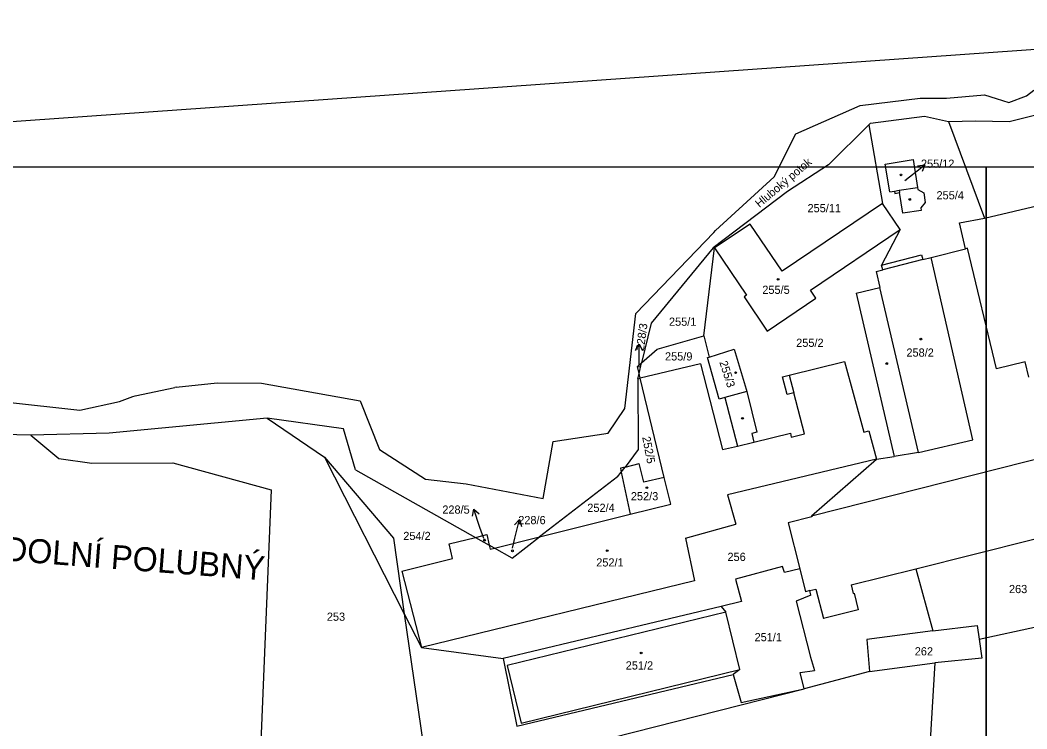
# Model space of a CAD drawing. Extents: x -670359 to -668019, y -978807 to -976674.
# Drawn here: x -669575.5 to -669366.6, y -977116.7 to -976969.5 of the extents above; entities that cross this region are included whole.
import ezdxf

# ---------------------------------------------------------------- set-up
doc = ezdxf.new("R2010")
doc.units = 0
for name, color, linetype in [('Hranice kat_území', 7, 'Continuous'), ('Hranice parcel', 7, 'Continuous'), ('ML1000', 7, 'Continuous'), ('Parcelní čísla', 7, 'Continuous'), ('Pop  PČ popisy', 7, 'Continuous'), ('SO 11-10-01', 7, 'Continuous'), ('Vnitřní kresba', 7, 'Continuous'), ('Značky budov', 7, 'Continuous'), ('Značky kultur', 7, 'Continuous')]:
    doc.layers.add(name, color=color, linetype=linetype)

msp = doc.modelspace()

# ---------------------------------------------------------------- linework, layer by layer
at = {"layer": 'Defpoints'}
msp.add_line((-669278.09, -976969.54), (-669697.04, -976999.11), dxfattribs=at)
at = {"layer": 'Hranice kat_území'}
for points in [[(-669383.24, -976985.74), (-669375.35, -976985.08)], [(-669375.35, -976985.08), (-669372.93, -976985.84)], [(-669370.32, -976986.66), (-669366.61, -976985.24)], [(-669366.61, -976985.24), (-669365.09, -976984.06)], [(-669414.53, -976993.17), (-669401.13, -976987.24)], [(-669401.13, -976987.24), (-669388.7, -976985.73)], [(-669388.7, -976985.73), (-669383.24, -976985.74)], [(-669372.93, -976985.84), (-669370.32, -976986.66)], [(-669418.98, -977002.09), (-669414.53, -976993.17)], [(-669431.16, -977013.24), (-669418.98, -977002.09)], [(-669447.74, -977030.42), (-669431.53, -977013.62)], [(-669431.53, -977013.62), (-669431.16, -977013.24)], [(-669450, -977050.14), (-669447.74, -977030.42)], [(-669551.59, -977047.54), (-669543.38, -977045.77)], [(-669543.12, -977045.72), (-669543.38, -977045.77)], [(-669543.12, -977045.72), (-669534.58, -977044.84)], [(-669534.58, -977044.84), (-669525.37, -977044.9)], [(-669525.37, -977044.9), (-669504.89, -977048.55)], [(-669554.86, -977048.71), (-669552.1, -977047.65)], [(-669552.1, -977047.65), (-669551.59, -977047.54)], [(-669578.74, -977048.77), (-669563.12, -977050.54)], [(-669563.12, -977050.54), (-669554.86, -977048.71)], [(-669504.89, -977048.55), (-669500.91, -977058.64)], [(-669453.46, -977055.29), (-669450, -977050.14)], [(-669464.85, -977056.99), (-669453.46, -977055.29)], [(-669500.91, -977058.64), (-669491.39, -977064.86)], [(-669466.98, -977068.84), (-669464.85, -977056.99)], [(-669491.39, -977064.86), (-669482.95, -977065.82)], [(-669482.95, -977065.82), (-669466.98, -977068.84)]]:
    msp.add_lwpolyline(points, dxfattribs=at)
at = {"layer": 'Hranice parcel'}
for points in [[(-669398.99, -976990.92), (-669387.84, -976989.47)], [(-669387.84, -976989.47), (-669382.81, -976990.56)], [(-669370.26, -976990.58), (-669363.59, -976988.89)], [(-669407.72, -976999.55), (-669399.36, -976991.28)], [(-669398.99, -976990.92), (-669399.36, -976991.28)], [(-669399.36, -976991.28), (-669396.52, -977007.58)], [(-669382.81, -976990.56), (-669377.15, -976990.43)], [(-669382.81, -976990.56), (-669375.35, -977010.62)], [(-669377.15, -976990.43), (-669370.26, -976990.58)], [(-669407.72, -976999.55), (-669416.25, -977005.08)], [(-669395.01, -977005.17), (-669395.94, -976999.41), (-669390.17, -976998.48), (-669389.26, -977004.25)], [(-669375.35, -977010.62), (-669338.45, -977001.93)], [(-669389.26, -977004.25), (-669389.19, -977004.72)], [(-669416.25, -977005.08), (-669431.7, -977016.79)], [(-669395.01, -977005.17), (-669394.06, -977005.02)], [(-669394.06, -977005.02), (-669393.98, -977005.51), (-669393, -977005.35)], [(-669389.19, -977004.72), (-669387.97, -977005.42), (-669387.64, -977007.41), (-669388.58, -977008.51), (-669388.5, -977009.05), (-669392.31, -977009.62), (-669393, -977005.35)], [(-669396.52, -977007.58), (-669417.33, -977021.64)], [(-669392.85, -977013.01), (-669396.52, -977007.58)], [(-669380.54, -977011.61), (-669375.35, -977010.62)], [(-669424.02, -977011.91), (-669431.42, -977016.79)], [(-669417.33, -977021.64), (-669424.02, -977011.91)], [(-669379.29, -977017.02), (-669380.54, -977011.61)], [(-669411.46, -977025.59), (-669392.85, -977013.01)], [(-669392.85, -977013.01), (-669396.73, -977020.39)], [(-669431.7, -977016.79), (-669444.5, -977032.45)], [(-669433.62, -977035.07), (-669431.42, -977016.79)], [(-669431.7, -977016.79), (-669431.42, -977016.79)], [(-669431.42, -977016.79), (-669424.75, -977026.65)], [(-669386.42, -977018.82), (-669379.29, -977017.02)], [(-669378.87, -977016.91), (-669379.29, -977017.02)], [(-669372.89, -977041.92), (-669378.87, -977016.91)], [(-669396.73, -977020.39), (-669388.44, -977018.29)], [(-669388.44, -977018.29), (-669388.19, -977019.26)], [(-669388.19, -977019.26), (-669386.42, -977018.82)], [(-669377.79, -977056.66), (-669386.42, -977018.82)], [(-669396.48, -977021.36), (-669396.73, -977020.39)], [(-669397.84, -977021.7), (-669396.48, -977021.36)], [(-669397.84, -977021.7), (-669397.06, -977025.06)], [(-669402, -977026.22), (-669397.06, -977025.06)], [(-669424.75, -977026.65), (-669425.25, -977026.99)], [(-669425.25, -977026.99), (-669420.46, -977034.08)], [(-669420.46, -977034.08), (-669410.34, -977027.24)], [(-669410.34, -977027.24), (-669411.46, -977025.59)], [(-669402, -977026.22), (-669394.09, -977060.1)], [(-669444.5, -977032.45), (-669446.51, -977040.7)], [(-669443.28, -977037.86), (-669433.62, -977035.07)], [(-669433.62, -977035.07), (-669432.49, -977039.48)], [(-669446.51, -977040.7), (-669443.28, -977037.86)], [(-669432.49, -977039.48), (-669427.3, -977037.82)], [(-669427.3, -977037.82), (-669424.8, -977046.18)], [(-669432.87, -977039.6), (-669432.49, -977039.48)], [(-669430.4, -977048.22), (-669432.87, -977039.6)], [(-669447.38, -977041.47), (-669446.51, -977040.7)], [(-669447.04, -977042.9), (-669447.38, -977041.47)], [(-669447.04, -977042.9), (-669446.51, -977040.7)], [(-669434.29, -977040.86), (-669446.81, -977043.86)], [(-669434.29, -977040.86), (-669429.75, -977058.7)], [(-669415.92, -977043.26), (-669404.38, -977040.39)], [(-669404.38, -977040.39), (-669400.43, -977055.09)], [(-669366.93, -977040.49), (-669372.89, -977041.92)], [(-669366.18, -977043.64), (-669366.93, -977040.49)], [(-669447.3, -977043.97), (-669447.04, -977042.9)], [(-669447.3, -977043.97), (-669446.81, -977043.86)], [(-669447.3, -977043.97), (-669447.2, -977058.7)], [(-669441.81, -977064.46), (-669446.81, -977043.86)], [(-669417.28, -977043.62), (-669415.92, -977043.26)], [(-669416.3, -977047.29), (-669417.28, -977043.62)], [(-669424.8, -977046.18), (-669424.68, -977046.61)], [(-669429.25, -977047.9), (-669430.4, -977048.22)], [(-669429.25, -977047.9), (-669426.64, -977057.95)], [(-669424.68, -977046.61), (-669422.59, -977055.11)], [(-669414.95, -977046.93), (-669416.3, -977047.29)], [(-669412.69, -977055.44), (-669414.95, -977046.93)], [(-669524.19, -977052.18), (-669557.04, -977055.26)], [(-669508.4, -977054.4), (-669524.19, -977052.18)], [(-669524.19, -977052.18), (-669512.31, -977060.26)], [(-669573.27, -977055.67), (-669619.98, -977054.59)], [(-669505.9, -977062.9), (-669508.4, -977054.4)], [(-669411.24, -977072.45), (-669333.62, -977052.81)], [(-669557.04, -977055.26), (-669573.27, -977055.67)], [(-669573.27, -977055.67), (-669567.49, -977060.51)], [(-669422.59, -977055.11), (-669423.62, -977055.37)], [(-669423.62, -977055.37), (-669423.26, -977057.13)], [(-669423.26, -977057.13), (-669415.65, -977055.28)], [(-669415.65, -977055.28), (-669415.45, -977056.1)], [(-669415.45, -977056.1), (-669412.69, -977055.44)], [(-669400.43, -977055.09), (-669399.37, -977054.81)], [(-669399.37, -977054.81), (-669397.79, -977060.7)], [(-669389.08, -977059.29), (-669377.79, -977056.66)], [(-669447.2, -977058.7), (-669449.93, -977062.31)], [(-669429.75, -977058.7), (-669426.64, -977057.95)], [(-669426.64, -977057.95), (-669423.26, -977057.13)], [(-669567.49, -977060.51), (-669560.61, -977061.51)], [(-669512.31, -977060.26), (-669495.77, -977092.76)], [(-669397.79, -977060.7), (-669428.7, -977068.08)], [(-669411.24, -977072.45), (-669397.79, -977060.7)], [(-669397.79, -977060.7), (-669394.09, -977060.1)], [(-669389.08, -977059.29), (-669394.09, -977060.1)], [(-669560.61, -977061.51), (-669543.81, -977061.41)], [(-669543.81, -977061.41), (-669523.39, -977067.04)], [(-669505.9, -977062.9), (-669481, -977076.92)], [(-669450.74, -977063.38), (-669449.93, -977062.31)], [(-669449.93, -977062.31), (-669447.03, -977061.61)], [(-669446.09, -977065.49), (-669447.03, -977061.61)], [(-669451.51, -977064.38), (-669467.68, -977076.8)], [(-669451.51, -977064.38), (-669450.74, -977063.38)], [(-669450.74, -977063.38), (-669448.9, -977072.13)], [(-669441.81, -977064.46), (-669446.09, -977065.49)], [(-669440.46, -977070.03), (-669441.81, -977064.46)], [(-669523.39, -977067.04), (-669525.65, -977122.76)], [(-669428.7, -977068.08), (-669426.99, -977074.14)], [(-669448.9, -977072.13), (-669440.46, -977070.03)], [(-669389.6, -977083.42), (-669341.17, -977071.24)], [(-669467.68, -977076.8), (-669448.9, -977072.13)], [(-669411.19, -977072.65), (-669416.11, -977073.89)], [(-669411.24, -977072.45), (-669411.19, -977072.65)], [(-669437.4, -977077.05), (-669426.99, -977074.14)], [(-669416.11, -977073.89), (-669413.71, -977083.42)], [(-669486.48, -977078.28), (-669481, -977076.92)], [(-669481, -977076.92), (-669478.67, -977076.34)], [(-669481, -977076.92), (-669478.12, -977078.54)], [(-669478.67, -977076.34), (-669478.12, -977078.54)], [(-669477.06, -977079.14), (-669467.68, -977076.8)], [(-669473.4, -977081.2), (-669467.68, -977076.8)], [(-669437.4, -977077.05), (-669435.56, -977085.94)], [(-669485.73, -977081.29), (-669486.48, -977078.28)], [(-669477.06, -977079.14), (-669478.12, -977078.54)], [(-669473.4, -977081.2), (-669477.06, -977079.14)], [(-669496.31, -977083.92), (-669485.73, -977081.29)], [(-669417.26, -977082.95), (-669427.01, -977085.57)], [(-669416.86, -977084.23), (-669417.26, -977082.95)], [(-669413.71, -977083.42), (-669416.86, -977084.23)], [(-669413.71, -977083.42), (-669412.51, -977088.2)], [(-669403.06, -977086.8), (-669389.6, -977083.42)], [(-669389.6, -977083.42), (-669386.08, -977096.35)], [(-669496.31, -977083.92), (-669492.19, -977099.78)], [(-669435.56, -977085.94), (-669492.19, -977099.78)], [(-669427.01, -977085.57), (-669425.78, -977090.2)], [(-669411.61, -977087.97), (-669412.51, -977088.2)], [(-669411.61, -977087.97), (-669410.33, -977087.65)], [(-669411.39, -977088.91), (-669411.61, -977087.97)], [(-669410.33, -977087.65), (-669408.79, -977093.76)], [(-669403.06, -977086.8), (-669402.62, -977088.55)], [(-669411.39, -977088.91), (-669414.43, -977090.13)], [(-669414.43, -977090.13), (-669411.48, -977101.78)], [(-669402.62, -977088.55), (-669402.43, -977088.5)], [(-669402.43, -977088.5), (-669401.56, -977091.94)], [(-669430.01, -977091.26), (-669475.22, -977102.08)], [(-669425.78, -977090.2), (-669430.01, -977091.26)], [(-669430.01, -977091.26), (-669429.04, -977092.43)], [(-669401.56, -977091.94), (-669408.79, -977093.76)], [(-669495.77, -977092.76), (-669492.19, -977099.78)], [(-669426.11, -977104.37), (-669429.04, -977092.43)], [(-669376.48, -977098.05), (-669352.25, -977092.79)], [(-669386.08, -977096.35), (-669399.75, -977098.11)], [(-669386.08, -977096.35), (-669376.89, -977095.18)], [(-669376.89, -977095.18), (-669376.48, -977098.05)], [(-669399.75, -977098.11), (-669399.23, -977104.74)], [(-669376.48, -977098.05), (-669375.9, -977101.96)], [(-669492.19, -977099.78), (-669475.22, -977102.08)], [(-669475.22, -977102.08), (-669472.42, -977116.13)], [(-669411.48, -977101.78), (-669410.67, -977104.57)], [(-669375.9, -977101.96), (-669385.65, -977102.98)], [(-669426.11, -977104.37), (-669427.54, -977105.39)], [(-669413.63, -977104.99), (-669410.67, -977104.57)], [(-669399.23, -977104.74), (-669385.65, -977102.98)], [(-669385.65, -977102.98), (-669386.82, -977122.57)], [(-669472.42, -977116.13), (-669427.54, -977105.39)], [(-669427.54, -977105.39), (-669425.83, -977111.21)], [(-669412.81, -977108.34), (-669413.63, -977104.99)], [(-669425.83, -977111.21), (-669412.81, -977108.34)]]:
    msp.add_lwpolyline(points, dxfattribs=at)
at = {"layer": 'ML1000'}
for points in [[(-669375, -977000), (-669375, -977500), (-670000, -977500), (-670000, -977000)], [(-668750, -977000), (-668750, -977500), (-669375, -977500), (-669375, -977000)]]:
    msp.add_lwpolyline(points, close=True, dxfattribs=at)
at = {"layer": 'Parcelní čísla'}
for p, q in [((-669389.25, -976999.8), (-669387.77, -976999.57)), ((-669391.87, -977002.85), (-669390.89, -977002.07)), ((-669447.8, -977038.1), (-669447.05, -977036.8)), ((-669447.05, -977041.56), (-669447.05, -977040.8)), ((-669481.64, -977072.53), (-669481.34, -977071.06)), ((-669472.92, -977074.3), (-669471.89, -977073.21)), ((-669479.29, -977077.18), (-669480.07, -977074.85)), ((-669473.3, -977079.17), (-669472.81, -977077.1))]:
    msp.add_line(p, q, dxfattribs=at)
for points in [[(-669390.89, -977002.07), (-669387.77, -976999.57), (-669388.31, -977000.97)], [(-669447.05, -977040.8), (-669447.05, -977036.8), (-669446.3, -977038.1)], [(-669480.07, -977074.85), (-669481.34, -977071.06), (-669480.21, -977072.05)], [(-669472.81, -977077.1), (-669471.89, -977073.21), (-669471.46, -977074.65)]]:
    msp.add_lwpolyline(points, dxfattribs=at)
at = {"layer": 'Vnitřní kresba'}
for points in [[(-669393.08, -977004.86), (-669389.26, -977004.25)], [(-669394.06, -977005.02), (-669393.08, -977004.86)], [(-669393.08, -977004.86), (-669393, -977005.35)], [(-669388.19, -977019.26), (-669396.48, -977021.36)], [(-669389.08, -977059.29), (-669397.06, -977025.06)], [(-669446.81, -977043.86), (-669447.04, -977042.9)], [(-669415.92, -977043.26), (-669414.95, -977046.93)], [(-669424.68, -977046.61), (-669429.25, -977047.9)], [(-669512.31, -977060.26), (-669498.02, -977077.11)], [(-669449.93, -977062.31), (-669450.92, -977062.55)], [(-669450.92, -977062.55), (-669450.74, -977063.38)], [(-669498.02, -977077.11), (-669495.77, -977092.76)], [(-669478.12, -977078.54), (-669477.92, -977079.35)], [(-669477.92, -977079.35), (-669477.06, -977079.14)], [(-669495.77, -977092.76), (-669491.86, -977119.87)], [(-669429.04, -977092.43), (-669474.43, -977103.52)], [(-669474.43, -977103.52), (-669471.5, -977115.51)], [(-669471.5, -977115.51), (-669426.11, -977104.37)], [(-669399.23, -977104.74), (-669412.81, -977108.34)], [(-669483.62, -977126.35), (-669412.81, -977108.34)]]:
    msp.add_lwpolyline(points, dxfattribs=at)
at = {"layer": 'Značky budov'}
for centre in [(-669392.68, -977001.66), (-669418.19, -977023.36), (-669388.56, -977035.75), (-669427, -977042.73), (-669445.42, -977066.6), (-669453.65, -977079.67), (-669446.61, -977100.91)]:
    msp.add_circle(centre, 0.175, dxfattribs=at)
at = {"layer": 'Značky kultur'}
for centre in [(-669392.68, -977001.66), (-669390.86, -977006.76), (-669418.19, -977023.36), (-669388.56, -977035.75), (-669395.64, -977040.83), (-669427, -977042.73), (-669425.58, -977052.21), (-669445.42, -977066.6), (-669479.11, -977077.51), (-669473.33, -977079.71), (-669453.65, -977079.67), (-669446.61, -977100.91)]:
    msp.add_circle(centre, 0.175, dxfattribs=at)

# ---------------------------------------------------------------- texts
at = {"layer": 'Parcelní čísla'}
for s, height, p in [('255/12', 1.7, (-669388.55, -977000.19)), ('255/12', 0.1, (-669391.87, -977002.85)), ('255/4', 1.7, (-669385.32, -977006.75)), ('255/11', 1.7, (-669412.09, -977009.42)), ('255/5', 1.7, (-669421.47, -977026.37)), ('255/1', 1.7, (-669440.84, -977032.99)), ('255/2', 1.7, (-669414.44, -977037.37)), ('258/2', 1.7, (-669391.56, -977039.4)), ('255/9', 1.7, (-669441.66, -977040.19)), ('228/3', 0.1, (-669447.05, -977041.56)), ('252/3', 1.7, (-669448.75, -977069.22)), ('228/5', 1.7, (-669487.88, -977072)), ('252/4', 1.7, (-669457.79, -977071.63)), ('228/6', 1.7, (-669472.12, -977074.18)), ('254/2', 1.7, (-669495.98, -977077.47)), ('228/5', 0.1, (-669479.29, -977077.18)), ('228/6', 0.1, (-669473.3, -977079.17)), ('252/1', 1.7, (-669455.93, -977082.96)), ('256', 1.7, (-669428.7, -977081.81)), ('263', 1.7, (-669370.28, -977088.49)), ('253', 1.7, (-669511.84, -977094.23)), ('251/1', 1.7, (-669423.08, -977098.48)), ('262', 1.7, (-669389.83, -977101.42)), ('251/2', 1.7, (-669449.81, -977104.35))]:
    msp.add_text(s, height=height, dxfattribs=at).set_placement(p)
for s, rotation, p in [('228/3', 82.3739, (-669446.04, -977038.24)), ('255/3', 287.6844, (-669430.4, -977040.55)), ('252/5', 280.7912, (-669446.4, -977056.13))]:
    msp.add_text(s, height=1.7, rotation=rotation, dxfattribs=at).set_placement(p)
at = {"layer": 'Pop  PČ popisy'}
msp.add_text('Hluboký potok', height=1.7, rotation=40.144, dxfattribs=at).set_placement((-669422.06, -977008.55))
at = {"layer": 'SO 11-10-01'}
msp.add_text('dopr. DOLNÍ POLUBNÝ', height=5, rotation=355.6391, dxfattribs=at).set_placement((-669596.04, -977080.42))

doc.saveas('drawing.dxf')
